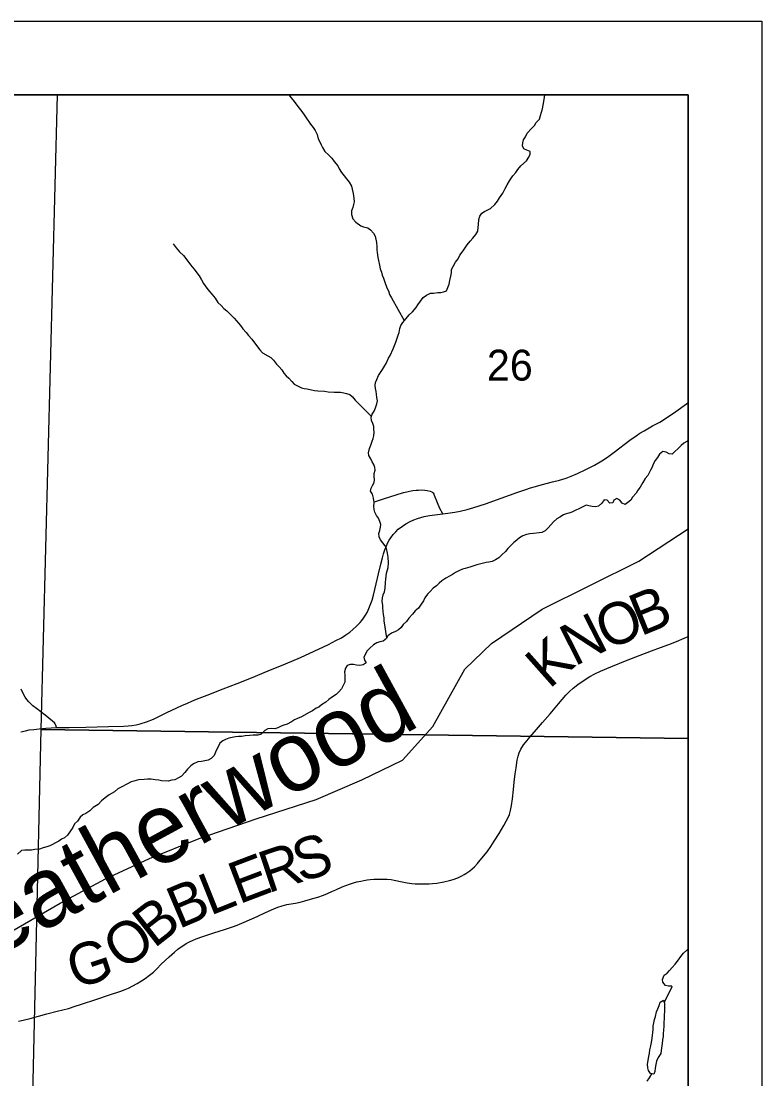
# Model space of a CAD drawing. Extents: x 0 to 34, y -8.9 to 22.
# Drawn here: x 29.611 to 30.617, y 12.568 to 14.004 of the extents above; entities that cross this region are included whole.
import ezdxf

# ---------------------------------------------------------------- set-up
doc = ezdxf.new("R2010")
doc.units = 0
for name, color, linetype in [('GM_X_Corporation', 7, 'Continuous'), ('GM_X_County_Road', 7, 'Continuous'), ('GM_X_Minor_River', 7, 'Continuous'), ('GM_X_Minor_River_Text', 7, 'Continuous'), ('GM_X_Rail_Line', 7, 'Continuous'), ('GM_X_Section_Text', 7, 'Continuous'), ('GM_X_State_Route', 7, 'Continuous'), ('GM_X_Township_Road', 7, 'Continuous'), ('GM_X_Township_Road_Text', 7, 'Continuous'), ('SH_Data', 7, 'Continuous')]:
    doc.layers.add(name, color=color, linetype=linetype)

msp = doc.modelspace()

# ---------------------------------------------------------------- linework, layer by layer
at = {"layer": 'GM_X_Corporation'}
for points in [[(28.7046, 7.104), (30.5167, 7.104), (30.5167, 13.904), (28.8143, 13.904), (28.8122, 13.7561), (28.8049, 13.053), (28.7787, 12.0377), (28.7786, 12.0342), (28.7779, 11.9899), (28.7762, 11.8872), (28.7797, 11.7437), (28.7775, 11.7346), (28.7754, 11.6346), (28.7651, 11.3014), (28.7622, 11.1187), (28.7609, 11.0119), (28.7377, 10.2012), (28.7308, 9.4444), (28.7238, 9.1729), (28.7123, 8.2818)], [(30.5167, 12.0118), (30.5167, 13.904), (28.8143, 13.904), (28.8122, 13.7561), (28.8049, 13.053), (28.7787, 12.0377), (28.8128, 12.0371), (28.9225, 12.0359), (29.2718, 12.0324), (29.364, 12.0313)], [(30.5167, 13.0305), (30.5167, 13.904), (29.6604, 13.904), (29.638, 13.0426)], [(30.5167, 12.0133), (30.5167, 13.0305), (29.638, 13.0426), (29.6152, 12.0286)]]:
    msp.add_lwpolyline(points, close=True, dxfattribs=at)
at = {"layer": 'GM_X_County_Road'}
msp.add_lwpolyline([(29.6594, 13.0451), (29.6585, 13.0484), (29.6577, 13.0501), (29.6567, 13.0516), (29.6541, 13.054), (29.6441, 13.0621), (29.6323, 13.0711), (29.6275, 13.0748), (29.6253, 13.0766), (29.6217, 13.0803), (29.6193, 13.0835), (29.6169, 13.0867), (29.6142, 13.0916), (29.6114, 13.0973)], dxfattribs=at)
at = {"layer": 'GM_X_Minor_River'}
for points in [[(29.9747, 13.904), (29.9777, 13.9), (29.982, 13.8948), (29.987, 13.888), (29.9924, 13.8813), (29.9963, 13.8753), (30.0041, 13.8644), (30.0079, 13.8596), (30.0103, 13.8558), (30.013, 13.8502), (30.0146, 13.8442), (30.017, 13.8404), (30.0186, 13.8363), (30.0205, 13.8325), (30.0236, 13.8273), (30.0286, 13.8228), (30.0333, 13.8179), (30.0364, 13.8135), (30.041, 13.8075), (30.043, 13.8037), (30.0461, 13.7988), (30.0496, 13.794), (30.053, 13.7902), (30.0565, 13.7854), (30.0596, 13.7801), (30.0608, 13.776), (30.0621, 13.7699), (30.0629, 13.7639), (30.0634, 13.759), (30.0627, 13.7552), (30.0617, 13.751), (30.0598, 13.7464), (30.0599, 13.7418), (30.0615, 13.7358), (30.0658, 13.731), (30.0723, 13.7261), (30.0761, 13.7247), (30.0818, 13.7233), (30.0856, 13.7207), (30.0895, 13.7162), (30.0918, 13.7121), (30.0935, 13.7034), (30.094, 13.6981), (30.0941, 13.6935), (30.0945, 13.6898), (30.0954, 13.6833), (30.0962, 13.6792), (30.0978, 13.6728), (30.0987, 13.6679), (30.1003, 13.6633), (30.1015, 13.6592), (30.103, 13.6554), (30.105, 13.6498), (30.1078, 13.6422), (30.1098, 13.6381), (30.1114, 13.6332), (30.1141, 13.6287), (30.1314, 13.5976)], [(30.181, 13.6359), (30.1847, 13.6368), (30.1885, 13.638), (30.1907, 13.6426), (30.1921, 13.6471), (30.1932, 13.6521), (30.1946, 13.6578), (30.1953, 13.6624), (30.1956, 13.6669), (30.2007, 13.6769), (30.2044, 13.6815), (30.2069, 13.6864), (30.2114, 13.6922), (30.214, 13.6964), (30.2169, 13.7003), (30.221, 13.7053), (30.2243, 13.7095), (30.2284, 13.7145), (30.231, 13.7191), (30.2316, 13.724), (30.2323, 13.7278), (30.2326, 13.735), (30.234, 13.7392), (30.2366, 13.7434), (30.2404, 13.7458), (30.2441, 13.7474), (30.2482, 13.7497), (30.2542, 13.7551), (30.2579, 13.7597), (30.2608, 13.7643), (30.2653, 13.7705), (30.2682, 13.777), (30.2711, 13.782), (30.2744, 13.7873), (30.2785, 13.7942), (30.2826, 13.7988), (30.2855, 13.8027), (30.2896, 13.8077), (30.2971, 13.8146), (30.3004, 13.8196), (30.3022, 13.8235), (30.3021, 13.8272), (30.2976, 13.8287), (30.2937, 13.8309), (30.2918, 13.835), (30.2921, 13.8388), (30.2932, 13.843), (30.2961, 13.8468), (30.2983, 13.8518), (30.3039, 13.8584), (30.308, 13.8626), (30.3105, 13.8664), (30.315, 13.8711), (30.3164, 13.876), (30.3175, 13.8806), (30.3189, 13.8852), (30.32, 13.8901), (30.3206, 13.895), (30.3217, 13.9007), (30.3223, 13.904)], [(29.8177, 13.702), (29.8216, 13.6963), (29.8262, 13.6911), (29.8316, 13.6859), (29.8362, 13.6799), (29.8413, 13.6732), (29.8459, 13.668), (29.8529, 13.6582), (29.856, 13.653), (29.8587, 13.6481), (29.8634, 13.6417), (29.8672, 13.6372), (29.8703, 13.6335), (29.8746, 13.6279), (29.8785, 13.6223), (29.8827, 13.6182), (29.8866, 13.6141), (29.8904, 13.6107), (29.9004, 13.6011), (29.9039, 13.5973), (29.9093, 13.591), (29.9124, 13.5865), (29.917, 13.5816), (29.9201, 13.5775), (29.9247, 13.5723), (29.9321, 13.5622), (29.9352, 13.5577), (29.9391, 13.554), (29.9463, 13.5499), (29.9501, 13.5473), (29.954, 13.544), (29.9579, 13.5384), (29.9617, 13.5347), (29.9652, 13.5309), (29.9679, 13.5264), (29.971, 13.5227), (29.9748, 13.5194), (29.9787, 13.5149), (29.9818, 13.5111), (29.9917, 13.5064), (29.9955, 13.5053), (29.9997, 13.505), (30.0096, 13.5029), (30.0141, 13.5022), (30.0232, 13.5016), (30.0281, 13.501), (30.0361, 13.5003), (30.0448, 13.5005), (30.0494, 13.4994), (30.0532, 13.4987), (30.0573, 13.4973), (30.0612, 13.494), (30.0647, 13.4898), (30.087, 13.4676)], [(30.1078, 13.167), (30.1039, 13.1903), (30.1042, 13.1941), (30.1034, 13.1986), (30.1025, 13.2077), (30.1024, 13.2115), (30.1016, 13.2164), (30.1019, 13.2214), (30.1029, 13.2255), (30.1044, 13.2294), (30.1054, 13.2343), (30.106, 13.2423), (30.1063, 13.2468), (30.1066, 13.2506), (30.1073, 13.2548), (30.1095, 13.2624), (30.1101, 13.2689), (30.1096, 13.2765), (30.1087, 13.2821), (30.1071, 13.2882), (30.1056, 13.2919), (30.1025, 13.2961), (30.099, 13.3002), (30.0974, 13.3043), (30.0969, 13.3088), (30.0984, 13.3127), (30.0991, 13.3172), (30.0994, 13.321), (30.0982, 13.3248), (30.0962, 13.3293), (30.0935, 13.333), (30.0915, 13.3376), (30.0907, 13.3413), (30.0902, 13.3455), (30.0905, 13.3508), (30.0897, 13.3565), (30.0881, 13.3621), (30.0857, 13.3663), (30.0864, 13.3701), (30.0882, 13.3739), (30.0904, 13.3777), (30.0911, 13.3815), (30.0907, 13.3864), (30.0906, 13.3902), (30.0917, 13.3944), (30.0916, 13.3982), (30.09, 13.4023), (30.0877, 13.4061), (30.0861, 13.4099), (30.0834, 13.4144), (30.0829, 13.4181), (30.0843, 13.4239), (30.0858, 13.4284), (30.088, 13.4338), (30.0894, 13.4376), (30.0901, 13.4414), (30.0904, 13.446), (30.0903, 13.4501), (30.0899, 13.4539), (30.0887, 13.4581), (30.0871, 13.4618), (30.0866, 13.4664), (30.0877, 13.4705), (30.0907, 13.4748), (30.0925, 13.479), (30.0943, 13.4847), (30.095, 13.4889), (30.0941, 13.493), (30.0937, 13.4976), (30.0932, 13.5013), (30.0924, 13.5055), (30.0919, 13.5097), (30.0923, 13.5135), (30.0941, 13.5177), (30.0963, 13.523), (30.0992, 13.5272), (30.1018, 13.5314), (30.1047, 13.5357), (30.1066, 13.5395), (30.1102, 13.5464), (30.1121, 13.5502), (30.1161, 13.5594), (30.1182, 13.564), (30.1201, 13.5685), (30.1219, 13.5739), (30.1233, 13.5777), (30.1244, 13.5815), (30.1254, 13.5868), (30.1269, 13.591), (30.1294, 13.5952), (30.1339, 13.6006), (30.138, 13.6052), (30.1424, 13.6095), (30.1476, 13.6153), (30.1498, 13.6191), (30.1572, 13.6291), (30.1617, 13.6322), (30.167, 13.6346), (30.1711, 13.635), (30.1768, 13.6355), (30.181, 13.6359)], [(30.5167, 13.4351), (30.5148, 13.4334), (30.5107, 13.431), (30.507, 13.4279), (30.5025, 13.4237), (30.4988, 13.4198), (30.495, 13.4163), (30.4909, 13.4166), (30.4867, 13.4192), (30.4825, 13.4199), (30.4776, 13.4164), (30.4751, 13.4118), (30.4721, 13.4076), (30.4692, 13.4026), (30.4677, 13.3988), (30.4655, 13.3946), (30.4619, 13.3873), (30.4582, 13.3831), (30.4552, 13.3777), (30.4516, 13.3716), (30.4482, 13.3674), (30.446, 13.3632), (30.4412, 13.3581), (30.439, 13.3539), (30.4349, 13.3505), (30.4311, 13.3481)], [(30.4311, 13.3481), (30.427, 13.3499), (30.4239, 13.3537), (30.4197, 13.3562), (30.4159, 13.3539), (30.4145, 13.3501), (30.4103, 13.35), (30.4068, 13.3537), (30.4027, 13.3541), (30.3997, 13.3498), (30.3952, 13.3456), (30.3907, 13.3447), (30.3862, 13.3454), (30.382, 13.3461), (30.3782, 13.3472), (30.3692, 13.3425), (30.3632, 13.3397), (30.359, 13.3377), (30.3549, 13.3361), (30.3511, 13.3353), (30.3474, 13.3341), (30.3425, 13.331), (30.3384, 13.3283), (30.3339, 13.3244), (30.3302, 13.3205), (30.3269, 13.3163), (30.3228, 13.3121), (30.3183, 13.3101), (30.3145, 13.3093), (30.3066, 13.3084), (30.302, 13.3083), (30.2971, 13.3071), (30.2922, 13.3055), (30.2878, 13.3027), (30.284, 13.2996), (30.2799, 13.2962), (30.2762, 13.2923), (30.2721, 13.2881), (30.2688, 13.2842), (30.2636, 13.2796), (30.2595, 13.2757), (30.255, 13.273), (30.2505, 13.2706), (30.2463, 13.2698), (30.2425, 13.2693), (30.2369, 13.2677), (30.2297, 13.2661), (30.2256, 13.2649), (30.2203, 13.2629), (30.2139, 13.2612), (30.2102, 13.26), (30.2064, 13.2585), (30.2008, 13.2557), (30.1967, 13.253), (30.1929, 13.2506), (30.188, 13.2479), (30.1824, 13.2444), (30.1787, 13.2413), (30.175, 13.2378), (30.1705, 13.2343), (30.1664, 13.2301), (30.1631, 13.2262), (30.1594, 13.2212), (30.1575, 13.2174), (30.1535, 13.2113), (30.1505, 13.2071), (30.1464, 13.2036), (30.1424, 13.199), (30.1375, 13.1936), (30.1342, 13.1893), (30.1297, 13.1851), (30.1271, 13.1812), (30.1234, 13.1778), (30.1193, 13.1758), (30.114, 13.1734), (30.1092, 13.1699), (30.1074, 13.1661), (30.1029, 13.1626), (30.0984, 13.1614), (30.0942, 13.1602), (30.0897, 13.1575), (30.0845, 13.1532), (30.0808, 13.149), (30.0786, 13.1448), (30.0764, 13.1409), (30.0776, 13.1368), (30.0795, 13.133), (30.0754, 13.1303), (30.0709, 13.1295), (30.0664, 13.1301), (30.0626, 13.1308), (30.058, 13.1307), (30.0539, 13.1295), (30.0517, 13.1257), (30.0502, 13.1208), (30.0507, 13.1162), (30.0508, 13.1117), (30.0505, 13.1067), (30.0483, 13.1021), (30.0461, 13.0979), (30.0428, 13.0937)], [(30.0428, 13.0937), (30.039, 13.0902), (30.0338, 13.0871), (30.0289, 13.0832), (30.0248, 13.0797), (30.0192, 13.0759), (30.0155, 13.0731), (30.0117, 13.0716), (30.0069, 13.0681), (30.0024, 13.0657), (29.9919, 13.0598), (29.9863, 13.0575), (29.9825, 13.0555), (29.9784, 13.0528), (29.9724, 13.05), (29.9679, 13.0484), (29.9641, 13.0472), (29.9596, 13.0449), (29.9558, 13.0436), (29.9509, 13.0439), (29.9464, 13.0435), (29.9423, 13.0411), (29.9371, 13.0361), (29.9325, 13.0349), (29.9265, 13.0348), (29.9216, 13.0343), (29.9155, 13.0338), (29.911, 13.033), (29.9065, 13.0329), (29.9023, 13.0325), (29.8932, 13.0308), (29.8887, 13.0292), (29.885, 13.0272), (29.8813, 13.0241), (29.8791, 13.0199), (29.8772, 13.0161), (29.875, 13.0119), (29.8732, 13.0073), (29.8691, 13.0031), (29.8654, 13.0011), (29.8609, 12.9999), (29.856, 12.9991), (29.851, 12.9986), (29.8454, 12.9958), (29.8417, 12.9935), (29.8372, 12.9889), (29.8335, 12.9843), (29.8291, 12.9792), (29.8249, 12.9769), (29.8201, 12.9745), (29.8159, 12.9737), (29.811, 12.9725), (29.8019, 12.9731), (29.7981, 12.9738), (29.7932, 12.9745), (29.7879, 12.9751), (29.783, 12.9754), (29.7784, 12.9749), (29.7705, 12.9741), (29.7645, 12.9724), (29.7607, 12.9716), (29.7547, 12.9685), (29.7483, 12.9649), (29.7427, 12.9622), (29.7382, 12.9579), (29.7311, 12.954), (29.7255, 12.9498), (29.7207, 12.9459), (29.7158, 12.9409), (29.7091, 12.9366), (29.7046, 12.9323), (29.699, 12.9288), (29.6953, 12.9269), (29.6915, 12.9234), (29.6878, 12.9184), (29.6837, 12.9145), (29.6816, 12.9096), (29.6782, 12.905), (29.6745, 12.8992), (29.6701, 12.8957), (29.6663, 12.8937), (29.6626, 12.891), (29.6581, 12.8887), (29.6539, 12.8867), (29.6502, 12.8847), (29.6464, 12.8832), (29.6415, 12.8819), (29.6363, 12.8803), (29.6299, 12.8795), (29.6253, 12.879), (29.6166, 12.8788), (29.6117, 12.8784), (29.6065, 12.8734)], [(30.4943, 12.6941), (30.4898, 12.6941), (30.486, 12.6951), (30.4825, 12.6996), (30.4817, 12.7034), (30.4842, 12.7091), (30.488, 12.7118), (30.4913, 12.7157), (30.495, 12.7196), (30.4991, 12.7242), (30.5036, 12.7299), (30.5069, 12.7346), (30.5102, 12.7388), (30.5147, 12.743), (30.5167, 12.7451)], [(30.4843, 12.672), (30.4955, 12.6942)], [(30.4654, 12.5757), (30.463, 12.5798), (30.4618, 12.5836), (30.4614, 12.5885), (30.4631, 12.5988), (30.4641, 12.6034), (30.4648, 12.6076), (30.4662, 12.6133), (30.4669, 12.6178), (30.4679, 12.6235), (30.4686, 12.6315), (30.4692, 12.6353), (30.4692, 12.6399), (30.4702, 12.6444), (30.4709, 12.649), (30.4723, 12.6532), (30.4737, 12.6593), (30.4756, 12.6635), (30.4774, 12.6681), (30.4788, 12.6723), (30.4833, 12.675), (30.4845, 12.6712), (30.4847, 12.6606), (30.4841, 12.6542), (30.4841, 12.6496), (30.4838, 12.6458), (30.4835, 12.6397), (30.4833, 12.6348), (30.4826, 12.6295), (30.4827, 12.6257), (30.482, 12.6215), (30.4813, 12.6162), (30.48, 12.6071), (30.4796, 12.6029), (30.476, 12.5975), (30.4738, 12.5925), (30.4727, 12.588), (30.472, 12.583), (30.4714, 12.5785), (30.4699, 12.5747), (30.4654, 12.5757)], [(30.461, 12.5654), (30.4643, 12.57), (30.4672, 12.5753)]]:
    msp.add_lwpolyline(points, dxfattribs=at)
at = {"layer": 'GM_X_Rail_Line'}
msp.add_lwpolyline([(28.7851, 11.9694), (28.7922, 11.9801), (28.8459, 12.0546), (28.9196, 12.1338), (29.0952, 12.3147), (29.27, 12.5091), (29.3099, 12.5609), (29.3494, 12.6008), (29.3988, 12.6397), (29.5756, 12.7558), (29.6642, 12.8069), (29.7261, 12.8401), (29.7857, 12.8674), (29.8529, 12.8945), (29.9302, 12.9215), (30.0116, 12.9474), (30.074, 12.9743), (30.1289, 13.0011), (30.1701, 13.0467), (30.2134, 13.1243), (30.2498, 13.1594), (30.3185, 13.2059), (30.4499, 13.2711), (30.5167, 13.3151)], dxfattribs=at)
at = {"layer": 'GM_X_State_Route'}
msp.add_lwpolyline([(29.6111, 13.0394), (29.6174, 13.041), (29.6225, 13.042), (29.6288, 13.0428), (29.6361, 13.0437), (29.6451, 13.0446), (29.6594, 13.0451), (29.6765, 13.0455), (29.6993, 13.0458), (29.7301, 13.0465), (29.7502, 13.0471), (29.7566, 13.0475), (29.7618, 13.0481), (29.7675, 13.0488), (29.773, 13.0501), (29.7815, 13.053), (29.7909, 13.0568), (29.809, 13.0656), (29.8296, 13.0752), (29.837, 13.0784), (29.8431, 13.0811), (29.8495, 13.0837), (29.8638, 13.0893), (29.8854, 13.0976), (29.9048, 13.1052), (29.924, 13.1128), (29.9468, 13.122), (29.97, 13.1315), (29.9906, 13.1404), (30.0091, 13.1488), (30.0219, 13.1549), (30.0284, 13.158), (30.0385, 13.1632), (30.046, 13.1672), (30.052, 13.1711), (30.0573, 13.1748), (30.0614, 13.1782), (30.0665, 13.1827), (30.0715, 13.1879), (30.0736, 13.1905), (30.076, 13.1937), (30.0787, 13.1978), (30.0809, 13.2015), (30.0823, 13.2044), (30.0844, 13.209), (30.0862, 13.2138), (30.0877, 13.2181), (30.0895, 13.2249), (30.0934, 13.2404), (30.0966, 13.254), (30.0997, 13.2669), (30.1018, 13.2758), (30.1033, 13.2811), (30.1051, 13.2863), (30.1073, 13.2918), (30.1093, 13.2962), (30.1111, 13.2995), (30.1131, 13.3028), (30.1164, 13.3072), (30.1199, 13.311), (30.1233, 13.3143), (30.1289, 13.3186), (30.1336, 13.3217), (30.1393, 13.3251), (30.1443, 13.3273), (30.1494, 13.3292), (30.1539, 13.3305), (30.1586, 13.3317), (30.1657, 13.3329), (30.1836, 13.3352), (30.1937, 13.3366), (30.1999, 13.3376), (30.2071, 13.3391), (30.2168, 13.3413), (30.2256, 13.3439), (30.2417, 13.3491), (30.2631, 13.3566), (30.2855, 13.3646), (30.2963, 13.3684), (30.3029, 13.3705), (30.3096, 13.3726), (30.3174, 13.3747), (30.3326, 13.3786), (30.342, 13.381), (30.3513, 13.3839), (30.3579, 13.3864), (30.3664, 13.3899), (30.378, 13.3956), (30.3894, 13.4014), (30.3994, 13.4071), (30.4071, 13.4121), (30.4163, 13.4188), (30.4376, 13.4353), (30.4459, 13.4413), (30.4513, 13.4448), (30.4568, 13.4481), (30.4683, 13.4546), (30.478, 13.4599), (30.4873, 13.4656), (30.4999, 13.4743), (30.5145, 13.4848), (30.5167, 13.4864)], dxfattribs=at)
at = {"layer": 'GM_X_Township_Road'}
for points in [[(30.0911, 13.3517), (30.1047, 13.356), (30.1203, 13.361), (30.1304, 13.3642), (30.1347, 13.3653), (30.1384, 13.3662), (30.1432, 13.367), (30.1476, 13.3674), (30.1509, 13.3676), (30.1546, 13.3678), (30.1591, 13.3675), (30.1625, 13.3671), (30.1666, 13.3661), (30.1687, 13.3653)], [(30.1836, 13.3352), (30.1798, 13.3426), (30.1764, 13.3503), (30.1724, 13.3604), (30.1713, 13.3627), (30.1703, 13.364), (30.1687, 13.3653)], [(29.6079, 12.6467), (29.6141, 12.6479), (29.6237, 12.6503), (29.6464, 12.6565), (29.6603, 12.6602), (29.6756, 12.664), (29.6848, 12.6669), (29.6922, 12.6693), (29.7141, 12.6768), (29.7314, 12.6825), (29.7467, 12.6876), (29.7525, 12.6898), (29.757, 12.6916), (29.763, 12.6945), (29.7689, 12.6978), (29.7747, 12.7013), (29.7798, 12.7048), (29.7857, 12.7091), (29.7909, 12.7134), (29.7955, 12.7177), (29.8016, 12.7239), (29.8121, 12.7339), (29.8194, 12.7402), (29.8243, 12.7443), (29.8288, 12.7477), (29.832, 12.7499), (29.8353, 12.752), (29.8399, 12.7545), (29.8447, 12.7568), (29.8488, 12.7585), (29.8578, 12.7617), (29.8728, 12.7666), (29.8874, 12.7713), (29.8981, 12.7749), (29.9044, 12.7772), (29.9108, 12.7798), (29.9244, 12.7855), (29.9319, 12.7889), (29.9432, 12.7943), (29.9545, 12.7993), (29.9599, 12.8015), (29.9655, 12.8033), (29.9722, 12.805), (29.9749, 12.8056), (29.9837, 12.807), (29.9899, 12.8082), (29.9966, 12.8099), (30.0073, 12.813), (30.0143, 12.8151), (30.0217, 12.8178), (30.0273, 12.82), (30.0342, 12.823), (30.0385, 12.825), (30.0473, 12.829), (30.0519, 12.8309), (30.0569, 12.8328), (30.0624, 12.8346), (30.0671, 12.8357), (30.0723, 12.8368), (30.0767, 12.8376), (30.0811, 12.8385), (30.0849, 12.8389), (30.0901, 12.8394), (30.095, 12.8395), (30.1018, 12.8396), (30.1084, 12.8394), (30.1137, 12.8388), (30.1176, 12.8382), (30.1287, 12.8358), (30.1355, 12.8346), (30.1418, 12.8337), (30.1463, 12.8333), (30.1522, 12.8329), (30.1653, 12.8331), (30.1697, 12.8334), (30.1758, 12.8342), (30.1849, 12.8359), (30.1926, 12.8376), (30.1976, 12.8391), (30.204, 12.8414), (30.2093, 12.8438), (30.2126, 12.8456), (30.215, 12.847), (30.2203, 12.8508), (30.2269, 12.8564), (30.2307, 12.8607), (30.2346, 12.8652), (30.2438, 12.8767), (30.2487, 12.8836), (30.2536, 12.8909), (30.2601, 12.9013), (30.2666, 12.9122), (30.2699, 12.918), (30.2721, 12.9224), (30.2741, 12.9274), (30.2756, 12.9325), (30.277, 12.9393), (30.2783, 12.9484), (30.2796, 12.9613), (30.2807, 12.9713), (30.282, 12.9822), (30.2832, 12.9907), (30.2845, 13.0008), (30.2858, 13.0062), (30.2874, 13.0107), (30.2896, 13.0158), (30.2933, 13.0217), (30.2957, 13.0249), (30.3019, 13.0321), (30.311, 13.0427), (30.3191, 13.0521), (30.3292, 13.064), (30.3409, 13.0775), (30.3507, 13.089), (30.3556, 13.0941), (30.3606, 13.0985), (30.3668, 13.1035), (30.3756, 13.1097), (30.3832, 13.1144), (30.3902, 13.1181), (30.3976, 13.1216), (30.4115, 13.1276), (30.4341, 13.1366), (30.4514, 13.1436), (30.4668, 13.1493), (30.4791, 13.1537), (30.4906, 13.1578), (30.5008, 13.162), (30.5111, 13.1664), (30.5167, 13.1688)]]:
    msp.add_lwpolyline(points, dxfattribs=at)
at = {"layer": 'SH_Data'}
for points in [[(23.6167, 14.004), (30.6167, 14.004), (30.6167, 7.004), (23.6167, 7.004)], [(23.7167, 13.904), (30.5167, 13.904), (30.5167, 7.104), (23.7167, 7.104)]]:
    msp.add_lwpolyline(points, close=True, dxfattribs=at)

# ---------------------------------------------------------------- texts
at = {"layer": 'GM_X_Minor_River_Text'}
msp.add_text('Leatherwood', height=0.094692, rotation=28.6221, dxfattribs=at).set_placement((29.5124, 12.6981))
at = {"layer": 'GM_X_Section_Text'}
msp.add_text('26', height=0.04186, rotation=0, dxfattribs=at).set_placement((30.2435, 13.5162))
at = {"layer": 'GM_X_Township_Road_Text'}
for s, rotation, p in [('B', 22.2218, (30.4522, 13.1688)), ('O', 22.3223, (30.4059, 13.1498)), ('N', 26.899, (30.3624, 13.1277)), ('K', 41.629, (30.3282, 13.0966)), ('S', 17.3756, (29.9903, 12.8348)), ('R', 18.5534, (29.9463, 12.82)), ('E', 20.7747, (29.9071, 12.8051)), ('B', 22.9198, (29.8252, 12.7714)), ('L', 21.7258, (29.8679, 12.7895)), ('B', 37.9456, (29.7918, 12.7447)), ('O', 35.8422, (29.7494, 12.7141)), ('G', 18.1516, (29.6849, 12.6898))]:
    msp.add_text(s, height=0.0568, rotation=rotation, dxfattribs=at).set_placement(p)

doc.saveas('drawing.dxf')
